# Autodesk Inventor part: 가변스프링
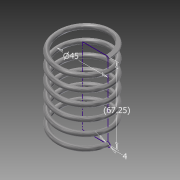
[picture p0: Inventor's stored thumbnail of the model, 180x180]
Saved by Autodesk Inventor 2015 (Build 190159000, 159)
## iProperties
Created: 2016-02
Part Number: 가변스프링
Material: 스테인레스 스틸
Document SubType Name: Modeling
Designer: Administrator
Mass: 84.2141 g
Surface Area: 106.444 cm^2
Volume: 10.5268 cm^3
Density: 8 g/cm^3
Appearance: 반연마
Author: Administrator
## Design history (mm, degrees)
sketch "스케치1"
  geometry: L1 (0, 0)-(-22.5, 0); L2 (-22.5, 0)-(-22.5, 67.25); L3 (-22.5, 67.25)-(0, 67.25); L4 (0, 67.25)-(0, 0); C1 r 2 at (-22.5, 0)
  constraints: 8 end point, 2 parallel, 1 centre point, 1 coincident, 1 horizontal, 1 perpendicular
  dimensions: "d0" = 45 diameter of L2 L4; "d1" = 67.25 distance between parallel lines of L1 L3 (derived); "d2" = 4 diameter of C1
feature "코일1" sketch "스케치1" pitch "d3" = 10; turns "d5" = 6; dims "d4" = 67.25 (= d1), "d6" = 0, angle "d7" = 90 deg, angle "d8" = 90 deg, "d9" = 0, "d10" = 0
sketch "스케치2"
  geometry: L1 (20.5, 0)-(24.5, 0) reference; 1 further point
  constraints: 1 horizontal alignment
extrude "돌출1" cut sketch "스케치2" stored distance "d11" = 10; taper "d12" = 0 deg
node "작업 평면1"
sketch "스케치3"
  geometry: L1 (-20.5, 0)-(-24.5, 0) reference; 1 further point
  constraints: 1 horizontal alignment
extrude "돌출2" cut sketch "스케치3" stored distance "d13" = 10; taper "d14" = 0 deg
node "솔리드1"
node "절단 모서리 투영1"
node "절단 모서리 투영2"
